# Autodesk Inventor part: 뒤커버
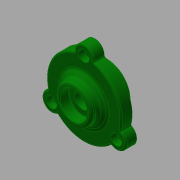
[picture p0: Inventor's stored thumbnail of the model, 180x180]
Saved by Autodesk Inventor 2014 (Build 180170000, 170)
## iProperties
Created: 2016-05
Part Number: 뒤커버
Document SubType Name: Modeling
Designer: mduedu
Density: 2.71 g/cm^3
Material: 알루미늄 6061
Appearance: 진녹색
Author: mduedu
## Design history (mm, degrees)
sketch "스케치1"
  geometry: C1 r 17.5 at (0, 0); C2 r 27.5 at (0, 0); 1 further point
  constraints: 2 centre point, 2 coincident
  dimensions: "d33" = 55 diameter of C2; "d34" = 35 diameter of C1
extrude "돌출1" new body sketch "스케치1" distance "d0" = 8; taper "d1" = 0 deg
extrude "돌출2" join sketch "스케치1" distance "d2" = 8; taper "d3" = 0 deg; dims "d35" = 9, "d36" = 0
sketch "스케치5"
  geometry: L1 (-27.5, 8)-(27.5, 8) reference; L2 (0, 0)-(0, 15); L3 (-27.5, 0)-(27.5, 0) reference; L4 (17.5, 8)-(0, 8); A1 r 25.375 centre (0, -10.375) between (17.5, 8) and (0, 15)
  constraints: 4 end point, 3 point on line, 2 point on circle, 1 centre point, 1 midpoint, 1 perpendicular
  dimensions: "d37" = 17.5 distance from line of L2 L4.start; "d39" = 7 distance from line of L1 L2.end
revolve "회전2" sketch "스케치5" stored, may be unused: angle "d40" = 90 deg
node "작업 평면1"
sketch "스케치6"
  geometry: C1 r 13.5 at (0, 0); 1 further point
  constraints: 1 centre point, 1 coincident
  dimensions: "d42" = 27 diameter of C1
extrude "돌출4" join sketch "스케치6" stored distance "d43" = 10; taper "d44" = 0 deg
sketch "스케치4"
  geometry: L1 (0, -9)-(0, 16); L2 (-15, -9)-(-15, 0); L3 (-15, 0)-(-10, 0); L4 (-10, 0)-(-10, 3); L5 (-10, 3)-(-6, 3); L6 (-6, 3)-(-6, 9); L7 (-6, 9)-(-10, 9); L8 (-10, 9)-(-10, 16); L9 (17.5, -9)-(-17.5, -9) reference; L10 (-13.5, 16)-(13.5, 16) reference; 1 further point
  constraints: 16 end point, 6 parallel, 3 point on line, 2 midpoint, 1 perpendicular, 1 vertical
  dimensions: "d15" = 30 diameter of L2 L1; "d16" = 20 diameter of L8 L1; "d18" = 9 distance of L2.start L2.end; "d19" = 3 distance of L3.end L4.end; "d20" = 20 diameter of L4 L1; "d21" = 12 diameter of L6 L1; "d45" = 7 distance of L7.end L8.end
revolve "회전1" sketch "스케치4" stored, may be unused: angle "d22" = 90 deg
fillet "모깎기2" dims "d23" = 3
fillet "모깎기3" dims "d24" = 0.3
chamfer "모따기2" distance "d46" = 0.5; stored, may be unused: second distance "d47" = 2, angle "d48" = 45 deg
fillet "모깎기4" dims "d49" = 3
fillet "모깎기5" dims "d50" = 2
sketch "스케치7"
  geometry: C1 r 7 at (0, 27.5); 2 further points
  constraints: 3 vertical alignment, 1 centre point, 2 other
  dimensions: "d54" = 14 diameter of C1
extrude "돌출5" join sketch "스케치7" stored distance "d55" = 10; taper "d56" = 0 deg
fillet "모깎기6" dims "d57" = 1
fillet "모깎기7" dims "d61" = 1
sketch "스케치8" dims "d62" = 55 (derived)
  geometry: C1 r 18.661 at (0, 0) reference; A1 r 2 centre (-7.999, 27.355) between (-7.437, 25.435) and (-5.999, 27.391) reference; A2 r 26.5 centre (0, 0) between (-7.437, 25.435) and (-25.746, -6.277) reference; A3 r 2 centre (-27.689, -6.75) between (-26.721, -8.5) and (-25.746, -6.277) reference; A4 r 6 centre (-23.816, -13.75) between (-26.721, -8.5) and (-20.722, -18.891) reference; A5 r 2 centre (-19.69, -20.604) between (-18.309, -19.158) and (-20.722, -18.891) reference; A6 r 26.5 centre (0, 0) between (-18.309, -19.158) and (18.309, -19.158) reference; A7 r 2 centre (19.69, -20.604) between (20.722, -18.891) and (18.309, -19.158) reference; A8 r 6 centre (23.816, -13.75) between (20.722, -18.891) and (26.721, -8.5) reference; A9 r 2 centre (27.689, -6.75) between (25.746, -6.277) and (26.721, -8.5) reference; A10 r 26.5 centre (0, 0) between (25.746, -6.277) and (7.437, 25.435) reference; A11 r 2 centre (7.999, 27.355) between (5.999, 27.391) and (7.437, 25.435) reference; A12 r 6 centre (0, 27.5) between (5.999, 27.391) and (-5.999, 27.391) reference; 4 further points
  constraints: 2 coincident, 1 vertical alignment, 6 other
  dimensions: "d65" = 360 deg dimension on A2.centre point (0, 27.5) (derived)
sketch "스케치9"
  geometry: 3 further points
  constraints: 3 other
hole "구멍2" sketch "스케치9" at (-23.816, -13.75), (23.816, -13.75), (0, 27.5) diameter "d67" = 4.5; stored, may be unused: countersink angle "d71" = 90 deg, drill point angle "d73" = 0 deg; dims "d68" = 6, "d69" = 8, "d70" = 4.6, "d72" = 8
node "솔리드1"
pattern_circular "원형 패턴1" dims angle "d59" = 360 deg
other parameters: "d41" = 8
